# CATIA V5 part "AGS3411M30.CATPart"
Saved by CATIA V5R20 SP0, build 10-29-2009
Part number: AGS3411M30
Definition: NONE
Nomenclature: AGS3411M30
Source: Unknown
Description: AGS3411M30
Bounding box of the stored display mesh (mm): x -35 to 33, y -17.347 to 17.347, z -16.458 to 16.458
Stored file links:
  C:\Users\Utente\Desktop\IO LAVORO\3D X SITO CF\X SITO\PLASTICA\AGS\AGS3411M30.CATPart
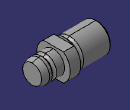
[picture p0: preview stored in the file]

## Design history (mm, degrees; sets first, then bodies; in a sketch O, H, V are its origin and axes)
Body1 "AGS3411M30" (main body)
  Solid1: solid without history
